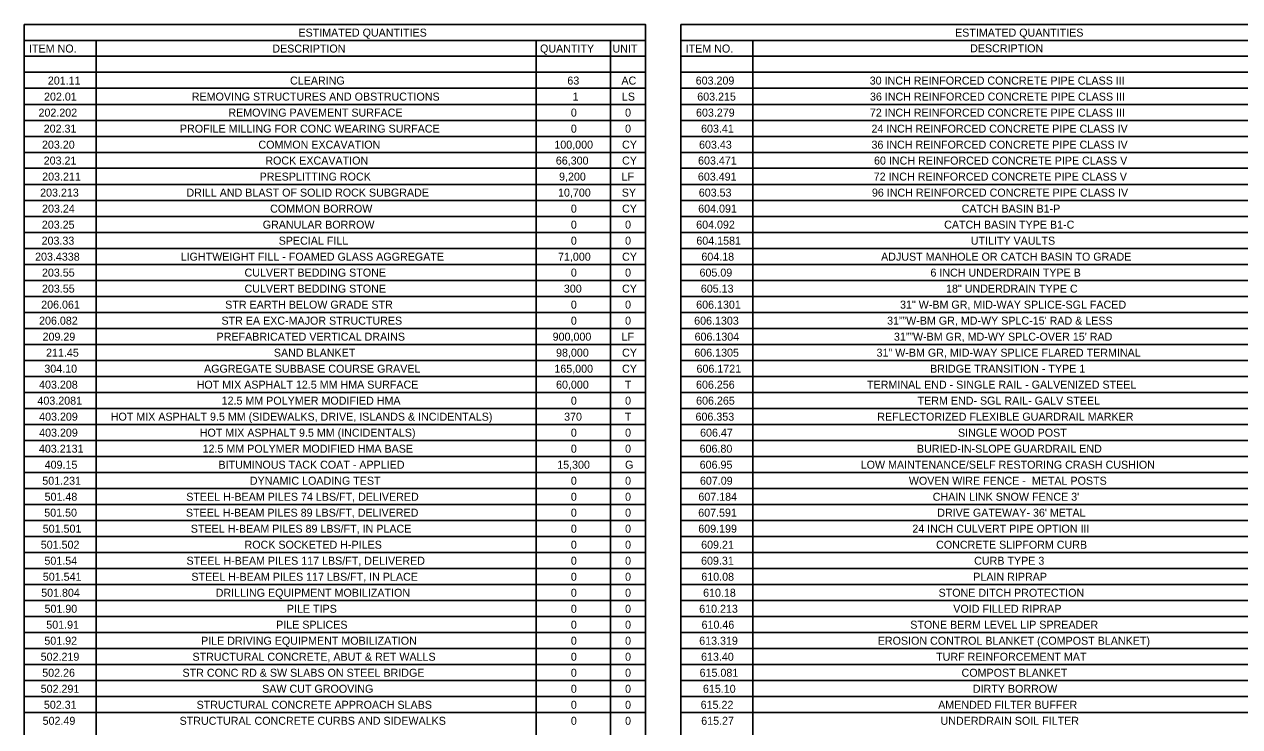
# Model space of a CAD drawing. Extents: x -18.7 to 5.6, y -2.7 to 5.1.
# Drawn here: x 3.137 to 4.632, y 0.887 to 1.751 of the extents above; entities that cross this region are included whole.
import ezdxf

# ---------------------------------------------------------------- set-up
doc = ezdxf.new("R2010")
doc.units = 0
doc.layers.add('ANNOTATION', color=7, linetype='Continuous')
doc.layers.add('BORDER', color=7, linetype='Continuous')

msp = doc.modelspace()

# ---------------------------------------------------------------- linework, layer by layer
at = {"layer": 'BORDER'}
for p, q in [((3.1369, 1.7315), (3.9012, 1.7315)), ((3.2255, 1.7315), (3.2255, 0.0189)), ((3.7669, 1.7315), (3.7669, 0.0189)), ((3.8583, 1.7315), (3.8583, 0.0189)), ((3.9448, 1.7315), (4.8091, 1.7315)), ((4.0334, 1.7315), (4.0334, 0.0189)), ((3.1369, 1.7119), (3.9012, 1.7119)), ((3.9448, 1.7119), (4.8091, 1.7119)), ((3.1369, 1.6922), (3.9012, 1.6922)), ((3.9448, 1.6922), (4.8091, 1.6922)), ((3.1369, 1.6725), (3.9012, 1.6725)), ((3.9448, 1.6725), (4.8091, 1.6725)), ((3.1369, 1.6528), (3.9012, 1.6528)), ((3.9448, 1.6528), (4.8091, 1.6528)), ((3.1369, 1.6331), (3.9012, 1.6331)), ((3.9448, 1.6331), (4.8091, 1.6331)), ((3.1369, 1.6134), (3.9012, 1.6134)), ((3.9448, 1.6134), (4.8091, 1.6134)), ((3.1369, 1.5937), (3.9012, 1.5937)), ((3.9448, 1.5937), (4.8091, 1.5937)), ((3.1369, 1.5741), (3.9012, 1.5741)), ((3.9448, 1.5741), (4.8091, 1.5741)), ((3.1369, 1.5544), (3.9012, 1.5544)), ((3.9448, 1.5544), (4.8091, 1.5544)), ((3.1369, 1.5347), (3.9012, 1.5347)), ((3.9448, 1.5347), (4.8091, 1.5347)), ((3.1369, 1.515), (3.9012, 1.515)), ((3.9448, 1.515), (4.8091, 1.515)), ((3.1369, 1.4953), (3.9012, 1.4953)), ((3.9448, 1.4953), (4.8091, 1.4953)), ((3.1369, 1.4756), (3.9012, 1.4756)), ((3.9448, 1.4756), (4.8091, 1.4756)), ((3.1369, 1.4559), (3.9012, 1.4559)), ((3.9448, 1.4559), (4.8091, 1.4559)), ((3.1369, 1.4363), (3.9012, 1.4363)), ((3.9448, 1.4363), (4.8091, 1.4363)), ((3.1369, 1.4166), (3.9012, 1.4166)), ((3.9448, 1.4166), (4.8091, 1.4166)), ((3.1369, 1.3969), (3.9012, 1.3969)), ((3.9448, 1.3969), (4.8091, 1.3969)), ((3.1369, 1.3772), (3.9012, 1.3772)), ((3.9448, 1.3772), (4.8091, 1.3772)), ((3.1369, 1.3575), (3.9012, 1.3575)), ((3.9448, 1.3575), (4.8091, 1.3575)), ((3.1369, 1.3378), (3.9012, 1.3378)), ((3.9448, 1.3378), (4.8091, 1.3378)), ((3.1369, 1.3181), (3.9012, 1.3181)), ((3.9448, 1.3181), (4.8091, 1.3181)), ((3.1369, 1.2985), (3.9012, 1.2985)), ((3.9448, 1.2985), (4.8091, 1.2985)), ((3.1369, 1.2788), (3.9012, 1.2788)), ((3.9448, 1.2788), (4.8091, 1.2788)), ((3.1369, 1.2591), (3.9012, 1.2591)), ((3.9448, 1.2591), (4.8091, 1.2591)), ((3.1369, 1.2394), (3.9012, 1.2394)), ((3.9448, 1.2394), (4.8091, 1.2394)), ((3.1369, 1.2197), (3.9012, 1.2197)), ((3.9448, 1.2197), (4.8091, 1.2197)), ((3.1369, 1.2), (3.9012, 1.2)), ((3.9448, 1.2), (4.8091, 1.2)), ((3.1369, 1.1803), (3.9012, 1.1803)), ((3.9448, 1.1803), (4.8091, 1.1803)), ((3.1369, 1.1607), (3.9012, 1.1607)), ((3.9448, 1.1607), (4.8091, 1.1607)), ((3.1369, 1.141), (3.9012, 1.141)), ((3.9448, 1.141), (4.8091, 1.141)), ((3.1369, 1.1213), (3.9012, 1.1213)), ((3.9448, 1.1213), (4.8091, 1.1213)), ((3.1369, 1.1016), (3.9012, 1.1016)), ((3.9448, 1.1016), (4.8091, 1.1016)), ((3.1369, 1.0819), (3.9012, 1.0819)), ((3.9448, 1.0819), (4.8091, 1.0819)), ((3.1369, 1.0622), (3.9012, 1.0622)), ((3.9448, 1.0622), (4.8091, 1.0622)), ((3.1369, 1.0425), (3.9012, 1.0425)), ((3.9448, 1.0425), (4.8091, 1.0425)), ((3.1369, 1.0229), (3.9012, 1.0229)), ((3.9448, 1.0229), (4.8091, 1.0229)), ((3.1369, 1.0032), (3.9012, 1.0032)), ((3.9448, 1.0032), (4.8091, 1.0032)), ((3.1369, 0.9835), (3.9012, 0.9835)), ((3.9448, 0.9835), (4.8091, 0.9835)), ((3.1369, 0.9638), (3.9012, 0.9638)), ((3.9448, 0.9638), (4.8091, 0.9638)), ((3.1369, 0.9441), (3.9012, 0.9441)), ((3.9448, 0.9441), (4.8091, 0.9441)), ((3.1369, 0.9244), (3.9012, 0.9244)), ((3.9448, 0.9244), (4.8091, 0.9244)), ((3.1369, 0.9047), (3.9012, 0.9047)), ((3.9448, 0.9047), (4.8091, 0.9047))]:
    msp.add_line(p, q, dxfattribs=at)
for points in [[(3.1369, 1.7512), (3.9012, 1.7512), (3.9012, 0.0189), (3.1369, 0.0189)], [(3.9448, 1.7512), (4.8091, 1.7512), (4.8091, 0.0189), (3.9448, 0.0189)]]:
    msp.add_lwpolyline(points, close=True, dxfattribs=at)

# ---------------------------------------------------------------- texts
at = {"layer": 'ANNOTATION'}
for s, height, p in [('201.11', 0.00984, (3.1659, 1.6771)), ('CLEARING', 0.00984, (3.4639, 1.6771)), ('63', 0.00984, (3.8051, 1.6771)), ('AC', 0.00984, (3.8716, 1.6771)), ('603.209', 0.00984, (3.963, 1.6771)), ('30 INCH REINFORCED CONCRETE PIPE CLASS III', 0.009843, (4.1771, 1.6771)), ('202.01', 0.00984, (3.1612, 1.6574)), ('REMOVING STRUCTURES AND OBSTRUCTIONS', 0.009843, (3.343, 1.6574)), ('1', 0.00984, (3.8115, 1.6574)), ('LS', 0.00984, (3.8722, 1.6574)), ('603.215', 0.00984, (3.9649, 1.6574)), ('36 INCH REINFORCED CONCRETE PIPE CLASS III', 0.009843, (4.1774, 1.6574)), ('202.202', 0.00984, (3.1544, 1.6377)), ('REMOVING PAVEMENT SURFACE', 0.009843, (3.388, 1.6377)), ('0', 0.00984, (3.8094, 1.6377)), ('0', 0.00984, (3.8761, 1.6377)), ('603.279', 0.00984, (3.9634, 1.6377)), ('72 INCH REINFORCED CONCRETE PIPE CLASS III', 0.009843, (4.1773, 1.6377)), ('202.31', 0.00984, (3.1608, 1.618)), ('PROFILE MILLING FOR CONC WEARING SURFACE', 0.009843, (3.3284, 1.618)), ('0', 0.00984, (3.8094, 1.618)), ('0', 0.00984, (3.8761, 1.618)), ('603.41', 0.00984, (3.9696, 1.618)), ('24 INCH REINFORCED CONCRETE PIPE CLASS IV', 0.009843, (4.1793, 1.618)), ('203.20', 0.00984, (3.1587, 1.5983)), ('COMMON EXCAVATION', 0.009843, (3.425, 1.5983)), ('100,000', 0.00984, (3.7891, 1.5983)), ('CY', 0.00984, (3.8724, 1.5983)), ('603.43', 0.00984, (3.9671, 1.5983)), ('36 INCH REINFORCED CONCRETE PIPE CLASS IV', 0.009843, (4.1793, 1.5983)), ('203.21', 0.00984, (3.1608, 1.5787)), ('ROCK EXCAVATION', 0.009843, (3.4335, 1.5787)), ('66,300', 0.00984, (3.7909, 1.5787)), ('CY', 0.00984, (3.8724, 1.5787)), ('603.471', 0.00984, (3.9659, 1.5787)), ('60 INCH REINFORCED CONCRETE PIPE CLASS V', 0.009843, (4.1824, 1.5787)), ('203.211', 0.00984, (3.1589, 1.559)), ('PRESPLITTING ROCK', 0.009843, (3.4265, 1.559)), ('9,200', 0.00984, (3.7949, 1.559)), ('LF', 0.00984, (3.8718, 1.559)), ('603.491', 0.00984, (3.9657, 1.559)), ('72 INCH REINFORCED CONCRETE PIPE CLASS V', 0.009843, (4.182, 1.559)), ('203.213', 0.00984, (3.1564, 1.5393)), ('DRILL AND BLAST OF SOLID ROCK SUBGRADE', 0.009843, (3.3364, 1.5393)), ('10,700', 0.00984, (3.7936, 1.5393)), ('SY', 0.00984, (3.872, 1.5393)), ('603.53', 0.00984, (3.9668, 1.5393)), ('96 INCH REINFORCED CONCRETE PIPE CLASS IV', 0.009843, (4.1798, 1.5393)), ('203.24', 0.00984, (3.1588, 1.5196)), ('COMMON BORROW', 0.009843, (3.4394, 1.5196)), ('0', 0.00984, (3.8094, 1.5196)), ('CY', 0.00984, (3.8724, 1.5196)), ('604.091', 0.00984, (3.9661, 1.5196)), ('CATCH BASIN B1-P', 0.009843, (4.2902, 1.5196)), ('203.25', 0.00984, (3.1585, 1.4999)), ('GRANULAR BORROW', 0.009843, (3.4303, 1.4999)), ('0', 0.00984, (3.8094, 1.4999)), ('0', 0.00984, (3.8761, 1.4999)), ('604.092', 0.00984, (3.9636, 1.4999)), ('CATCH BASIN TYPE B1-C', 0.009843, (4.2687, 1.4999)), ('203.33', 0.00984, (3.1582, 1.4802)), ('SPECIAL FILL', 0.009843, (3.4499, 1.4802)), ('0', 0.00984, (3.8094, 1.4802)), ('0', 0.00984, (3.8761, 1.4802)), ('604.1581', 0.00984, (3.9638, 1.4802)), ('UTILITY VAULTS', 0.009843, (4.3014, 1.4802)), ('203.4338', 0.00984, (3.1502, 1.4605)), ('LIGHTWEIGHT FILL - FOAMED GLASS AGGREGATE', 0.009843, (3.3293, 1.4605)), ('71,000', 0.00984, (3.7936, 1.4605)), ('CY', 0.00984, (3.8724, 1.4605)), ('604.18', 0.00984, (3.97, 1.4605)), ('ADJUST MANHOLE OR CATCH BASIN TO GRADE', 0.009843, (4.1911, 1.4605)), ('203.55', 0.00984, (3.1587, 1.4409)), ('CULVERT BEDDING STONE', 0.009843, (3.4079, 1.4409)), ('0', 0.00984, (3.8094, 1.4409)), ('0', 0.00984, (3.8761, 1.4409)), ('605.09', 0.00984, (3.9677, 1.4409)), ('6 INCH UNDERDRAIN TYPE B', 0.009843, (4.2518, 1.4409)), ('203.55', 0.00984, (3.1587, 1.4212)), ('CULVERT BEDDING STONE', 0.009843, (3.4079, 1.4212)), ('300', 0.00984, (3.8008, 1.4212)), ('CY', 0.00984, (3.8724, 1.4212)), ('605.13', 0.00984, (3.9693, 1.4212)), ('18" UNDERDRAIN TYPE C', 0.009843, (4.271, 1.4212)), ('206.061', 0.00984, (3.1577, 1.4015)), ('STR EARTH BELOW GRADE STR', 0.009843, (3.3841, 1.4015)), ('0', 0.00984, (3.8094, 1.4015)), ('0', 0.00984, (3.8761, 1.4015)), ('606.1301', 0.00984, (3.9636, 1.4015)), ('31" W-BM GR, MID-WAY SPLICE-SGL FACED', 0.009843, (4.2144, 1.4015)), ('206.082', 0.00984, (3.1551, 1.3818)), ('STR EA EXC-MAJOR STRUCTURES', 0.009843, (3.3795, 1.3818)), ('0', 0.00984, (3.8094, 1.3818)), ('0', 0.00984, (3.8761, 1.3818)), ('606.1303', 0.00984, (3.9611, 1.3818)), ("31””W-BM GR, MD-WY SPLC-15' RAD & LESS", 0.009843, (4.1985, 1.3818)), ('209.29', 0.00984, (3.1594, 1.3621)), ('PREFABRICATED VERTICAL DRAINS', 0.009843, (3.3735, 1.3621)), ('900,000', 0.00984, (3.787, 1.3621)), ('LF', 0.00984, (3.8718, 1.3621)), ('606.1304', 0.00984, (3.9616, 1.3621)), ("31””W-BM GR, MD-WY SPLC-OVER 15' RAD", 0.009843, (4.2069, 1.3621)), ('211.45', 0.00984, (3.1637, 1.3424)), ('SAND BLANKET', 0.009843, (3.444, 1.3424)), ('98,000', 0.00984, (3.7912, 1.3424)), ('CY', 0.00984, (3.8724, 1.3424)), ('606.1305', 0.00984, (3.9613, 1.3424)), ('31" W-BM GR, MID-WAY SPLICE FLARED TERMINAL', 0.009843, (4.1855, 1.3424)), ('304.10', 0.00984, (3.1616, 1.3227)), ('AGGREGATE SUBBASE COURSE GRAVEL', 0.009843, (3.3581, 1.3227)), ('165,000', 0.00984, (3.7891, 1.3227)), ('CY', 0.00984, (3.8724, 1.3227)), ('606.1721', 0.00984, (3.964, 1.3227)), ('BRIDGE TRANSITION - TYPE 1', 0.009843, (4.2514, 1.3227)), ('403.208', 0.00984, (3.1551, 1.3031)), ('HOT MIX ASPHALT 12.5 MM HMA SURFACE', 0.009843, (3.349, 1.3031)), ('60,000', 0.00984, (3.7912, 1.3031)), ('T', 0.00984, (3.8757, 1.3031)), ('606.256', 0.00984, (3.9634, 1.3031)), ('TERMINAL END - SINGLE RAIL - GALVENIZED STEEL', 0.009843, (4.1738, 1.3031)), ('403.2081', 0.00984, (3.1531, 1.2834)), ('12.5 MM POLYMER MODIFIED HMA', 0.009843, (3.3797, 1.2834)), ('0', 0.00984, (3.8094, 1.2834)), ('0', 0.00984, (3.8761, 1.2834)), ('606.265', 0.00984, (3.9635, 1.2834)), ('TERM END- SGL RAIL- GALV STEEL', 0.009843, (4.236, 1.2834)), ('403.209', 0.00984, (3.1552, 1.2637)), ('HOT MIX ASPHALT 9.5 MM (SIDEWALKS, DRIVE, ISLANDS & INCIDENTALS)', 0.009843, (3.2433, 1.2637)), ('370', 0.00984, (3.8011, 1.2637)), ('T', 0.00984, (3.8757, 1.2637)), ('606.353', 0.00984, (3.9628, 1.2637)), ('REFLECTORIZED FLEXIBLE GUARDRAIL MARKER', 0.009843, (4.1864, 1.2637)), ('403.209', 0.00984, (3.1552, 1.244)), ('HOT MIX ASPHALT 9.5 MM (INCIDENTALS)', 0.009843, (3.3528, 1.244)), ('0', 0.00984, (3.8094, 1.244)), ('0', 0.00984, (3.8761, 1.244)), ('606.47', 0.00984, (3.9684, 1.244)), ('SINGLE WOOD POST', 0.009843, (4.2857, 1.244)), ('403.2131', 0.00984, (3.1549, 1.2243)), ('12.5 MM POLYMER MODIFIED HMA BASE', 0.009843, (3.3563, 1.2243)), ('0', 0.00984, (3.8094, 1.2243)), ('0', 0.00984, (3.8761, 1.2243)), ('606.80', 0.00984, (3.9678, 1.2243)), ('BURIED-IN-SLOPE GUARDRAIL END', 0.009843, (4.2352, 1.2243)), ('409.15', 0.00984, (3.162, 1.2046)), ('BITUMINOUS TACK COAT - APPLIED', 0.009843, (3.3758, 1.2046)), ('15,300', 0.00984, (3.7926, 1.2046)), ('G', 0.00984, (3.8761, 1.2046)), ('606.95', 0.00984, (3.9679, 1.2046)), ('LOW MAINTENANCE/SELF RESTORING CRASH CUSHION', 0.009843, (4.166, 1.2046)), ('501.231', 0.00984, (3.1591, 1.1849)), ('DYNAMIC LOADING TEST', 0.009843, (3.4144, 1.1849)), ('0', 0.00984, (3.8094, 1.1849)), ('0', 0.00984, (3.8761, 1.1849)), ('607.09', 0.00984, (3.9682, 1.1849)), ('WOVEN WIRE FENCE -  METAL POSTS', 0.009843, (4.2252, 1.1849)), ('501.48', 0.00984, (3.1619, 1.1652)), ('STEEL H-BEAM PILES 74 LBS/FT, DELIVERED', 0.009843, (3.3362, 1.1652)), ('0', 0.00984, (3.8094, 1.1652)), ('0', 0.00984, (3.8761, 1.1652)), ('607.184', 0.00984, (3.9663, 1.1652)), ("CHAIN LINK SNOW FENCE 3'", 0.009843, (4.2546, 1.1652)), ('501.50', 0.00984, (3.1615, 1.1456)), ('STEEL H-BEAM PILES 89 LBS/FT, DELIVERED', 0.009843, (3.3358, 1.1456)), ('0', 0.00984, (3.8094, 1.1456)), ('0', 0.00984, (3.8761, 1.1456)), ('607.591', 0.00984, (3.9661, 1.1456)), ("DRIVE GATEWAY- 36' METAL", 0.009843, (4.2602, 1.1456)), ('501.501', 0.00984, (3.1596, 1.1259)), ('STEEL H-BEAM PILES 89 LBS/FT, IN PLACE', 0.009843, (3.3418, 1.1259)), ('0', 0.00984, (3.8094, 1.1259)), ('0', 0.00984, (3.8761, 1.1259)), ('609.199', 0.00984, (3.9662, 1.1259)), ('24 INCH CULVERT PIPE OPTION III', 0.009843, (4.2295, 1.1259)), ('501.502', 0.00984, (3.1572, 1.1062)), ('ROCK SOCKETED H-PILES', 0.009843, (3.4079, 1.1062)), ('0', 0.00984, (3.8094, 1.1062)), ('0', 0.00984, (3.8761, 1.1062)), ('609.21', 0.00984, (3.9697, 1.1062)), ('CONCRETE SLIPFORM CURB', 0.009843, (4.2588, 1.1062)), ('501.54', 0.00984, (3.1617, 1.0865)), ('STEEL H-BEAM PILES 117 LBS/FT, DELIVERED', 0.009843, (3.3365, 1.0865)), ('0', 0.00984, (3.8094, 1.0865)), ('0', 0.00984, (3.8761, 1.0865)), ('609.31', 0.00984, (3.9696, 1.0865)), ('CURB TYPE 3', 0.009843, (4.3056, 1.0865)), ('501.541', 0.00984, (3.1597, 1.0668)), ('STEEL H-BEAM PILES 117 LBS/FT, IN PLACE', 0.009843, (3.3425, 1.0668)), ('0', 0.00984, (3.8094, 1.0668)), ('0', 0.00984, (3.8761, 1.0668)), ('610.08', 0.00984, (3.9699, 1.0668)), ('PLAIN RIPRAP', 0.009843, (4.3045, 1.0668)), ('501.804', 0.00984, (3.1577, 1.0471)), ('DRILLING EQUIPMENT MOBILIZATION', 0.009843, (3.3724, 1.0471)), ('0', 0.00984, (3.8094, 1.0471)), ('0', 0.00984, (3.8761, 1.0471)), ('610.18', 0.00984, (3.9721, 1.0471)), ('STONE DITCH PROTECTION', 0.009843, (4.2618, 1.0471)), ('501.90', 0.00984, (3.1618, 1.0274)), ('PILE TIPS', 0.00984, (3.46, 1.0274)), ('0', 0.00984, (3.8094, 1.0274)), ('0', 0.00984, (3.8761, 1.0274)), ('610.213', 0.00984, (3.9673, 1.0274)), ('VOID FILLED RIPRAP', 0.009843, (4.2799, 1.0274)), ('501.91', 0.00984, (3.164, 1.0078)), ('PILE SPLICES', 0.009843, (3.4468, 1.0078)), ('0', 0.00984, (3.8094, 1.0078)), ('0', 0.00984, (3.8761, 1.0078)), ('610.46', 0.00984, (3.9702, 1.0078)), ('STONE BERM LEVEL LIP SPREADER ', 0.009843, (4.227, 1.0078)), ('501.92', 0.00984, (3.1616, 0.9881)), ('PILE DRIVING EQUIPMENT MOBILIZATION', 0.009843, (3.3544, 0.9881)), ('0', 0.00984, (3.8094, 0.9881)), ('0', 0.00984, (3.8761, 0.9881)), ('613.319', 0.00984, (3.9673, 0.9881)), ('EROSION CONTROL BLANKET (COMPOST BLANKET)', 0.009843, (4.187, 0.9881)), ('502.219', 0.00984, (3.1571, 0.9684)), ('STRUCTURAL CONCRETE, ABUT & RET WALLS', 0.009843, (3.3439, 0.9684)), ('0', 0.00984, (3.8094, 0.9684)), ('0', 0.00984, (3.8761, 0.9684)), ('613.40', 0.00984, (3.9696, 0.9684)), ('TURF REINFORCEMENT MAT', 0.009843, (4.2588, 0.9684)), ('502.26', 0.00984, (3.159, 0.9487)), ('STR CONC RD & SW SLABS ON STEEL BRIDGE', 0.009843, (3.3316, 0.9487)), ('0', 0.00984, (3.8094, 0.9487)), ('0', 0.00984, (3.8761, 0.9487)), ('615.081', 0.00984, (3.9678, 0.9487)), ('COMPOST BLANKET', 0.009843, (4.2901, 0.9487)), ('502.291', 0.00984, (3.1571, 0.929)), ('SAW CUT GROOVING', 0.009843, (3.4296, 0.929)), ('0', 0.00984, (3.8094, 0.929)), ('0', 0.00984, (3.8761, 0.929)), ('615.10', 0.00984, (3.9719, 0.929)), ('DIRTY BORROW', 0.009843, (4.304, 0.929)), ('502.31', 0.00984, (3.161, 0.9093)), ('STRUCTURAL CONCRETE APPROACH SLABS', 0.009843, (3.3489, 0.9093)), ('0', 0.00984, (3.8094, 0.9093)), ('0', 0.00984, (3.8761, 0.9093)), ('615.22', 0.00984, (3.9691, 0.9093)), ('AMENDED FILTER BUFFER', 0.009843, (4.2613, 0.9093)), ('502.49', 0.00984, (3.1595, 0.8896)), ('STRUCTURAL CONCRETE CURBS AND SIDEWALKS', 0.009843, (3.328, 0.8896)), ('0', 0.00984, (3.8094, 0.8896)), ('0', 0.00984, (3.8761, 0.8896)), ('615.27', 0.00984, (3.9698, 0.8896)), ('UNDERDRAIN SOIL FILTER', 0.009843, (4.2642, 0.8896))]:
    msp.add_text(s, height=height, dxfattribs=at).set_placement(p)
at = {"layer": 'BORDER'}
for s, height, p in [('ESTIMATED QUANTITIES', 0.009843, (3.4742, 1.7361)), ('ESTIMATED QUANTITIES', 0.009843, (4.2821, 1.7361)), ('ITEM NO.', 0.00984, (3.1428, 1.7165)), ('DESCRIPTION', 0.009843, (3.4421, 1.7165)), ('QUANTITY', 0.00984, (3.7715, 1.7165)), ('UNIT', 0.00984, (3.8606, 1.7165)), ('ITEM NO.', 0.00984, (3.9507, 1.7165)), ('DESCRIPTION', 0.009843, (4.3006, 1.7168))]:
    msp.add_text(s, height=height, dxfattribs=at).set_placement(p)

doc.saveas('drawing.dxf')
